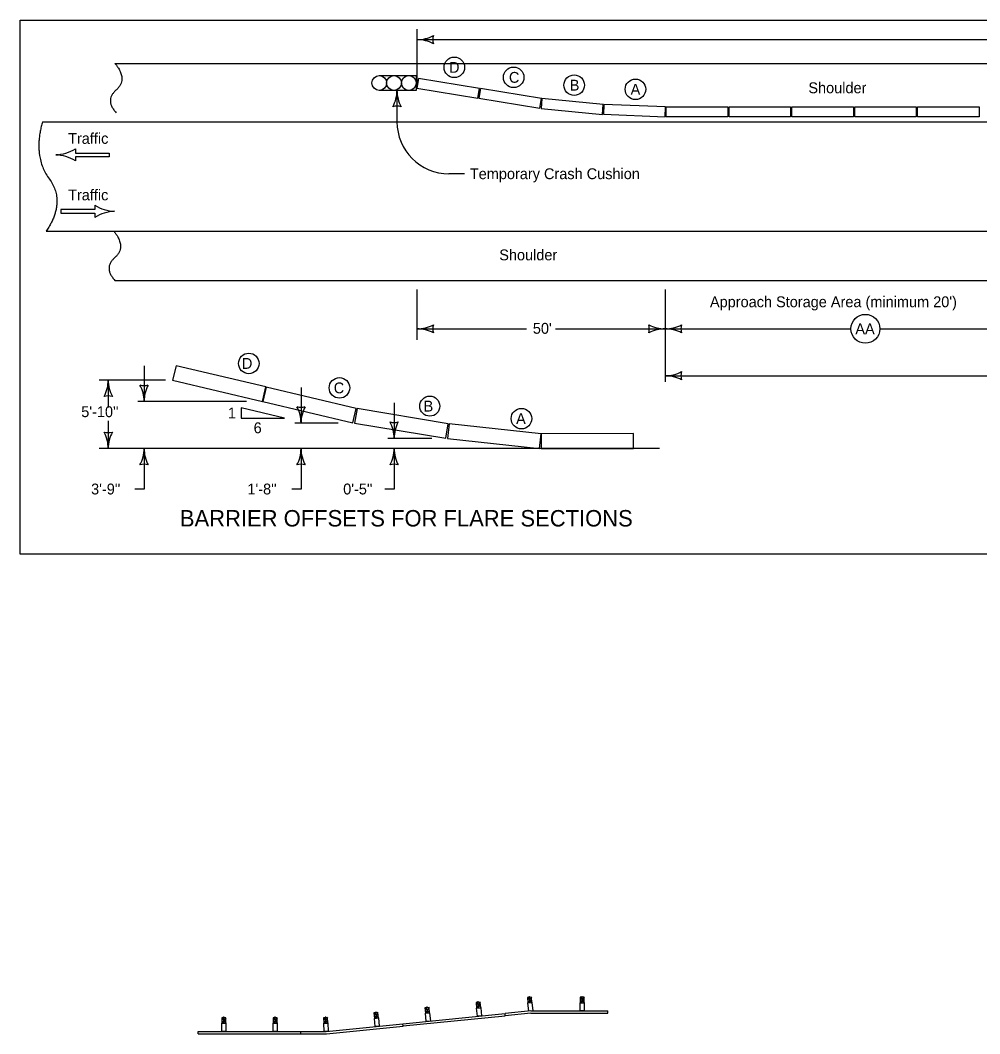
# Model space of a CAD drawing. Extents: x 6410 to 81668, y 3928 to 11667.
# Drawn here: x 10152 to 11320, y 10433 to 11667 of the extents above; entities that cross this region are included whole.
import ezdxf

# ---------------------------------------------------------------- set-up
doc = ezdxf.new("R2010")
doc.units = 0
doc.layers.add('dsnStdSection', color=7, linetype='Continuous')
doc.layers.add('Level 14', color=7, linetype='Continuous')

msp = doc.modelspace()

# ---------------------------------------------------------------- linework, layer by layer
at = {"layer": 'dsnStdSection'}
for p, q in [((10152.2, 11666.6), (13257.2, 11666.6)), ((10152.2, 11016.6), (10152.2, 11666.6)), ((10635.1, 11655.7), (10635.1, 11583.2)), ((10635.1, 11643), (11568, 11643)), ((10267.5, 11614), (11396, 11614)), ((10589.2, 11599.3), (10634.2, 11599.3)), ((10634.2, 11599.3), (10634.2, 11581.3)), ((10633, 11587), (10634.3, 11586.7)), ((10634.2, 11581.3), (10589.2, 11581.3)), ((10610.8, 11581.6), (10610.8, 11543)), ((10634.8, 11583.3), (10634.8, 11583.3)), ((10179.2, 11542.9), (11426, 11542.9)), ((10195.4, 11502.8), (10195.4, 11502.8)), ((10219.3, 11510.3), (10219.3, 11505)), ((10219.3, 11505), (10260.5, 11505)), ((10260.5, 11500.5), (10219.3, 11500.5)), ((10219.3, 11500.5), (10219.3, 11495.3)), ((10260.5, 11505), (10260.5, 11500.5)), ((10692.8, 11479.7), (10674.1, 11479.7)), ((10242.9, 11441.5), (10242.9, 11436.3)), ((10242.9, 11436.3), (10201.7, 11436.3)), ((10201.7, 11436.3), (10201.7, 11431.8)), ((10201.7, 11431.8), (10242.9, 11431.8)), ((10242.9, 11431.8), (10242.9, 11426.5)), ((10266.8, 11434), (10266.8, 11434)), ((10183.9, 11410), (11426, 11410)), ((10267.5, 11350), (11396, 11350)), ((10635.1, 11338.8), (10635.1, 11277.5)), ((10937.3, 11338.8), (10937.3, 11226.4)), ((10635.1, 11291), (10768.5, 11291)), ((10803.8, 11291), (10937.3, 11291)), ((10937.3, 11291), (11163.4, 11291)), ((11198.7, 11291), (11424.8, 11291)), ((10302.9, 11246.1), (10302.9, 11202.6)), ((10328.8, 11228.6), (10248.4, 11228.6)), ((10259.3, 11228.6), (10259.3, 11195.1)), ((10937.3, 11233.9), (11528.1, 11233.9)), ((10494, 11219.7), (10494, 11176.2)), ((10427.7, 11202.6), (10295.1, 11202.6)), ((10473.9, 11182.2), (10421.3, 11194.7)), ((10421.3, 11194.7), (10421.3, 11182.2)), ((10607.3, 11201.1), (10607.3, 11157.6)), ((10259.3, 11178.8), (10259.3, 11145.3)), ((10421.3, 11182.2), (10473.9, 11182.2)), ((10539, 11176.2), (10486.3, 11176.2)), ((10653.2, 11157.6), (10599.5, 11157.6)), ((10930.3, 11145.3), (10248.4, 11145.3)), ((10302.9, 11145.3), (10302.9, 11096)), ((10494, 11145.3), (10494, 11096)), ((10607.3, 11145.3), (10607.3, 11118.4)), ((10607.3, 11118.4), (10607.3, 11096)), ((10302.9, 11096), (10291.7, 11096)), ((10494, 11096), (10482.9, 11096)), ((10607.3, 11096), (10596.1, 11096)), ((13257.2, 11016.6), (10152.2, 11016.6))]:
    msp.add_line(p, q, dxfattribs=at)
for points in [[(10711.1, 11583.7), (10637, 11595.8), (10635.1, 11584), (10709.1, 11571.9)], [(10786.6, 11571.3), (10712.5, 11583.5), (10710.6, 11571.6), (10784.6, 11559.5)], [(10862, 11564.1), (10787.3, 11571.2), (10786.2, 11559.3), (10860.8, 11552.1)], [(10937.7, 11561.2), (10862.8, 11564.2), (10862.3, 11552.2), (10937.3, 11549.2)], [(10938.5, 11561.2), (11013.5, 11561.2), (11013.5, 11549.2), (10938.5, 11549.2)], [(11015, 11561.2), (11090, 11561.2), (11090, 11549.2), (11015, 11549.2)], [(11091.5, 11561.2), (11166.5, 11561.2), (11166.5, 11549.2), (11091.5, 11549.2)], [(11168, 11561.2), (11243, 11561.2), (11243, 11549.2), (11168, 11549.2)], [(11244.5, 11561.2), (11319.5, 11561.2), (11319.5, 11549.2), (11244.5, 11549.2)], [(10451.2, 11220.2), (10341.8, 11246.1), (10337.6, 11228.6), (10447.1, 11202.7)], [(10561, 11194.2), (10451.6, 11220.1), (10447.4, 11202.6), (10556.9, 11176.7)], [(10673.1, 11175.5), (10562.2, 11194), (10559.2, 11176.2), (10670.2, 11157.8)], [(10786.2, 11163.2), (10674.4, 11175.5), (10672.4, 11157.6), (10784.2, 11145.3)], [(10898.7, 11163.4), (10786.2, 11163.3), (10786.2, 11145.3), (10898.7, 11145.4)]]:
    msp.add_lwpolyline(points, close=True, dxfattribs=at)
for centre, radius in [((10680.6, 11609.3), 12.5), ((10752.8, 11597.1), 12.5), ((10589.2, 11590.3), 9), ((10589.2, 11590.3), 9), ((10607.2, 11590.3), 9), ((10607.2, 11590.3), 9), ((10625.2, 11590.3), 9), ((10625.2, 11590.3), 9), ((10826.5, 11587.6), 12.5), ((10901.1, 11582.6), 12.5), ((11181, 11291), 17.6), ((10430.4, 11248.9), 12.5), ((10540.7, 11219.1), 12.5), ((10650.7, 11196.9), 12.2), ((10762.3, 11181.7), 12.5)]:
    msp.add_circle(centre, radius, dxfattribs=at)
for centre, radius, start, end in [((10635.1, 11685.5), 42.5, 270, 298.0725), ((10670.7, 11643), 16.4, 162.2666, 197.7334), ((10635.1, 11600.5), 42.5, 61.9275, 90), ((10568.3, 11581.4), 42.5, 331.9275, 360), ((10653.3, 11581.4), 42.5, 180, 208.0725), ((10610.8, 11545.8), 16.4, 72.2666, 107.7334), ((10674.1, 11543), 63.3, 180, 270), ((10193.4, 11551.1), 48.4, 272.352, 302.382), ((10193.4, 11454.5), 48.4, 57.618, 87.648), ((10268.8, 11482.4), 48.4, 237.618, 267.648), ((10268.8, 11385.7), 48.4, 92.352, 122.382), ((10635.1, 11333.5), 42.5, 270, 298.0725), ((10635.1, 11248.5), 42.5, 61.9275, 90), ((10670.7, 11291), 16.4, 162.2666, 197.7334), ((10901.6, 11291), 16.4, 342.2666, 17.7333), ((10937.3, 11333.5), 42.5, 241.9275, 270), ((10937.3, 11248.5), 42.5, 90, 118.0725), ((10937.3, 11333.5), 42.5, 270, 298.0725), ((10937.3, 11248.5), 42.5, 61.9275, 90), ((10972.9, 11291), 16.4, 162.2666, 197.7334), ((10216.8, 11228.6), 42.5, 331.9275, 0), ((10301.8, 11228.6), 42.5, 180, 208.0725), ((10937.3, 11276.4), 42.5, 270, 298.0725), ((10937.3, 11191.4), 42.5, 61.9275, 90), ((10972.9, 11233.9), 16.4, 162.2666, 197.7334), ((10302.9, 11238.3), 16.4, 252.2666, 287.7334), ((10260.4, 11202.6), 42.5, 0, 28.0725), ((10345.4, 11202.6), 42.5, 151.9275, 180), ((10259.3, 11193), 16.4, 72.2666, 107.7334), ((10494, 11211.9), 16.4, 252.2666, 287.7334), ((10451.5, 11176.2), 42.5, 0, 28.0725), ((10536.5, 11176.2), 42.5, 151.9275, 180), ((10607.3, 11193.3), 16.4, 252.2666, 287.7334), ((10564.8, 11157.6), 42.5, 0, 28.0725), ((10649.8, 11157.6), 42.5, 151.9275, 180), ((10259.3, 11181), 16.4, 252.2666, 287.7334), ((10216.8, 11145.3), 42.5, 0, 28.0725), ((10301.8, 11145.3), 42.5, 151.9275, 180), ((10260.4, 11145.3), 42.5, 331.9275, 0), ((10345.4, 11145.3), 42.5, 180, 208.0725), ((10451.5, 11145.3), 42.5, 331.9275, 0), ((10536.5, 11145.3), 42.5, 180, 208.0725), ((10564.8, 11145.3), 42.5, 331.9275, 0), ((10649.8, 11145.3), 42.5, 180, 208.0725), ((10302.9, 11109.7), 16.4, 72.2666, 107.7334), ((10494, 11109.7), 16.4, 72.2666, 107.7334), ((10607.3, 11109.7), 16.4, 72.2666, 107.7334)]:
    msp.add_arc(centre, radius, start, end, dxfattribs=at)
for points in [[(10267.5, 11614), (10283.5, 11594.7), (10254.6, 11569.1), (10269.1, 11554.1)], [(10179.2, 11542.9), (10167.2, 11501.1), (10207.8, 11445.9), (10183.9, 11410)], [(10265.9, 11410), (10281.9, 11390.7), (10253, 11365.1), (10267.5, 11350)]]:
    msp.add_open_spline(points, degree=2, dxfattribs=at)
at = {"layer": 'Level 14'}
for p, q in [((10769.5, 10477), (10775.1, 10470.9)), ((10774.5, 10477.5), (10770.2, 10470.4)), ((10771.9, 10478.3), (10771.9, 10478.3)), ((10772.6, 10470.7), (10772, 10477.3)), ((10833.6, 10477.4), (10838.6, 10470.7)), ((10838.6, 10477.4), (10833.6, 10470.7)), ((10836.1, 10478.3), (10836.1, 10478.4)), ((10836.1, 10470.7), (10836.1, 10477.4)), ((10644.8, 10464.5), (10650.5, 10458.4)), ((10649.8, 10465), (10645.5, 10457.9)), ((10647.2, 10465.7), (10647.2, 10465.8)), ((10648, 10458.1), (10647.3, 10464.8)), ((10707, 10470.8), (10712.7, 10464.6)), ((10712, 10471.3), (10707.7, 10464.1)), ((10707.7, 10464.1), (10712.7, 10464.6)), ((10708.7, 10454.2), (10707.7, 10464.1)), ((10709.4, 10472), (10709.4, 10472)), ((10710.2, 10464.4), (10709.5, 10471)), ((10712.7, 10464.6), (10713.7, 10454.7)), ((10770.2, 10470.4), (10775.1, 10470.9)), ((10772.6, 10470.7), (10770.2, 10470.4)), ((10772.6, 10470.7), (10770.2, 10470.4)), ((10771.2, 10460.5), (10770.2, 10470.4)), ((10775.1, 10470.9), (10776.1, 10460.9)), ((10833.6, 10470.7), (10838.6, 10470.7)), ((10833.6, 10460.7), (10833.6, 10470.7)), ((10838.6, 10470.7), (10838.6, 10460.7)), ((10397.4, 10452.3), (10402.4, 10445.6)), ((10402.4, 10452.3), (10397.4, 10445.6)), ((10399.9, 10453.3), (10399.9, 10453.3)), ((10399.9, 10445.6), (10399.9, 10452.3)), ((10459.9, 10452.3), (10464.9, 10445.6)), ((10464.9, 10452.3), (10459.9, 10445.6)), ((10462.4, 10453.3), (10462.4, 10453.3)), ((10462.4, 10445.6), (10462.4, 10452.3)), ((10521.3, 10452.4), (10526.6, 10445.9)), ((10526.3, 10452.6), (10521.6, 10445.7)), ((10523.7, 10453.5), (10523.7, 10453.5)), ((10524.1, 10445.8), (10523.8, 10452.5)), ((10582.7, 10458.3), (10588.3, 10452.1)), ((10587.6, 10458.8), (10583.3, 10451.6)), ((10583.3, 10451.6), (10588.3, 10452.1)), ((10584.3, 10441.6), (10583.3, 10451.6)), ((10585.1, 10459.5), (10585, 10459.6)), ((10585.8, 10451.9), (10585.1, 10458.6)), ((10588.3, 10452.1), (10589.3, 10442.1)), ((10617.9, 10445), (10742.3, 10457.5)), ((10618.2, 10442.4), (10742.5, 10454.9)), ((10645.5, 10457.9), (10650.5, 10458.4)), ((10646.5, 10447.9), (10645.5, 10457.9)), ((10650.5, 10458.4), (10651.5, 10448.4)), ((10713.7, 10454.7), (10708.7, 10454.2)), ((10773.6, 10460.7), (10742.3, 10457.5)), ((10742.5, 10454.9), (10742.3, 10457.5)), ((10742.5, 10454.9), (10742.3, 10457.5)), ((10773.6, 10458), (10742.5, 10454.9)), ((10776.1, 10460.9), (10771.2, 10460.5)), ((10773.6, 10460.7), (10867.4, 10460.7)), ((10773.6, 10458), (10867.4, 10458)), ((10838.6, 10460.7), (10833.6, 10460.7)), ((10867.4, 10458), (10867.4, 10460.7)), ((10397.4, 10445.6), (10402.4, 10445.6)), ((10397.4, 10435.6), (10397.4, 10445.6)), ((10402.4, 10445.6), (10402.4, 10435.6)), ((10459.9, 10445.6), (10464.9, 10445.6)), ((10459.9, 10435.6), (10459.9, 10445.6)), ((10464.9, 10445.6), (10464.9, 10435.6)), ((10521.6, 10445.7), (10526.6, 10445.9)), ((10522.1, 10435.6), (10521.6, 10445.7)), ((10524.6, 10435.6), (10617.9, 10445)), ((10524.9, 10432.9), (10618.2, 10442.3)), ((10526.6, 10445.9), (10527.1, 10435.9)), ((10589.3, 10442.1), (10584.3, 10441.6)), ((10618.2, 10442.3), (10617.9, 10445)), ((10618.2, 10442.4), (10617.9, 10445)), ((10651.5, 10448.4), (10646.5, 10447.9)), ((10368.6, 10435.6), (10493.6, 10435.6)), ((10368.6, 10432.9), (10368.6, 10435.6)), ((10368.6, 10432.9), (10493.6, 10432.9)), ((10402.4, 10435.6), (10397.4, 10435.6)), ((10464.9, 10435.6), (10459.9, 10435.6)), ((10493.6, 10435.6), (10524.6, 10435.6)), ((10493.6, 10432.9), (10493.6, 10435.6)), ((10493.6, 10432.9), (10524.9, 10432.9)), ((10527.1, 10435.9), (10522.1, 10435.6))]:
    msp.add_line(p, q, dxfattribs=at)
for points in [[(10770.2, 10470.4), (10775.1, 10470.9), (10774.5, 10477.5), (10769.5, 10477)], [(10833.6, 10470.7), (10838.6, 10470.7), (10838.6, 10477.4), (10833.6, 10477.4)], [(10645.5, 10457.9), (10650.5, 10458.4), (10649.8, 10465), (10644.8, 10464.5)], [(10707.7, 10464.1), (10712.7, 10464.6), (10712, 10471.3), (10707, 10470.8)], [(10397.4, 10445.6), (10402.4, 10445.6), (10402.4, 10452.3), (10397.4, 10452.3)], [(10459.9, 10445.6), (10464.9, 10445.6), (10464.9, 10452.3), (10459.9, 10452.3)], [(10521.6, 10445.7), (10526.6, 10445.9), (10526.3, 10452.6), (10521.3, 10452.4)], [(10583.3, 10451.6), (10588.3, 10452.1), (10587.6, 10458.8), (10582.7, 10458.3)]]:
    msp.add_lwpolyline(points, close=True, dxfattribs=at)
for points in [[(10771.6, 10477.3), (10771.6, 10477.7), (10772.3, 10477.8), (10772.3, 10477.3)], [(10771.7, 10477.7), (10771.7, 10478.2), (10772.1, 10478.3), (10772.1, 10477.7)], [(10835.8, 10477.4), (10835.8, 10477.8), (10836.5, 10477.8), (10836.5, 10477.4)], [(10835.9, 10477.8), (10835.9, 10478.3), (10836.3, 10478.3), (10836.3, 10477.8)], [(10647.1, 10465.2), (10647, 10465.7), (10647.4, 10465.8), (10647.5, 10465.2)], [(10647, 10464.7), (10647, 10465.2), (10647.6, 10465.2), (10647.7, 10464.8)], [(10709.2, 10471), (10709.1, 10471.4), (10709.8, 10471.5), (10709.8, 10471)], [(10709.3, 10471.4), (10709.2, 10472), (10709.6, 10472), (10709.7, 10471.5)], [(10399.6, 10452.3), (10399.6, 10452.7), (10400.2, 10452.7), (10400.2, 10452.3)], [(10399.7, 10452.7), (10399.7, 10453.3), (10400.1, 10453.3), (10400.1, 10452.7)], [(10462.1, 10452.3), (10462.1, 10452.7), (10462.7, 10452.7), (10462.7, 10452.3)], [(10462.2, 10452.7), (10462.2, 10453.3), (10462.6, 10453.3), (10462.6, 10452.7)], [(10523.4, 10452.5), (10523.4, 10452.9), (10524.1, 10452.9), (10524.1, 10452.5)], [(10523.6, 10452.9), (10523.5, 10453.5), (10523.9, 10453.5), (10524, 10452.9)], [(10584.8, 10458.5), (10584.8, 10458.9), (10585.4, 10459), (10585.5, 10458.6)], [(10584.9, 10459), (10584.9, 10459.5), (10585.2, 10459.5), (10585.3, 10459)], [(10524.1, 10445.8), (10521.6, 10445.7), (10521.6, 10445.7)]]:
    msp.add_lwpolyline(points, dxfattribs=at)

# ---------------------------------------------------------------- texts
at = {"layer": 'dsnStdSection'}
for s, height, p in [('D', 13.2, (10674.2, 11602.7)), ('C', 13.2, (10747.1, 11590.5)), ('B', 13.2, (10821.1, 11581)), ('A', 13.2, (10895.2, 11576)), ('Shoulder', 13.2, (11111.6, 11577.8)), ('Traffic', 13.2, (10210.4, 11516.2)), ('Temporary Crash Cushion', 13.2, (10699.5, 11473.2)), ('Traffic', 13.2, (10210.4, 11447.4)), ('Shoulder', 13.2, (10735.3, 11374.4)), ("Approach Storage Area (minimum 20')", 13.2, (10991.8, 11317.3)), ("50'", 13.2, (10776.2, 11285)), ('AA', 13.2, (11168.8, 11284.4)), ('D', 13.2, (10422, 11242.3)), ('C', 13.2, (10533.8, 11212.5)), ('B', 13.2, (10643.2, 11190.3)), ("5'-10''", 13.2, (10226.4, 11183.5)), ('1', 13.2, (10404.9, 11182)), ('6', 13.2, (10436.3, 11163.9)), ('A', 13.2, (10755.8, 11175.1)), ("3'-9''", 13.2, (10238.4, 11089.4)), ("1'-8''", 13.2, (10428.7, 11089.4)), ("0'-5''", 13.2, (10545.3, 11089.4)), ('BARRIER OFFSETS FOR FLARE SECTIONS', 20, (10346.5, 11050.4))]:
    msp.add_text(s, height=height, dxfattribs=at).set_placement(p)

doc.saveas('drawing.dxf')
